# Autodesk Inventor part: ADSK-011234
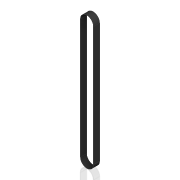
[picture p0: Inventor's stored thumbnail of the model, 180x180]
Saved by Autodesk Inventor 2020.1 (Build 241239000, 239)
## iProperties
Created: 1999-12
Part Number: ADSK-011234
Document SubType Name: Modeling
Designer: sspink
Material: Générique
Density: 1 g/cm^3
Appearance: Rubber-Black
Mass: 105.218 g
Surface Area: 1380.72 cm^2
Volume: 105.218 cm^3
Control State: 0
Master: False
Checked Out: False
Shininess: 0.0
Length Units: 11272
Angle Units: 11279
Time Units: 11290
Mass Units: 11286
Length Display Precision: 3
Angle Display Precision: 2
Compacted: True
Dimensions: 3,2x32,4x1,5 in
Mass: 0,232 lb
DocNumber: ADSK-011234.ipt
Folder: 01 - Themengebiete\Simplification\01 - Packaging machine\
VDS_Category: 3D Komponenten
Density: 0.0
Volumn: 0.0
Area: 0.0
PropertySet Name: Model Information
Author: sspink
Revision Number: -
Title: clutch
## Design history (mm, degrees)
node "Extrusion1" dims "d5" = 38.1635, "d6" = 0
workplane "Arbeitsebene1"
node "Solide1"
node "Corps solides"
node "Corps surfaciques"
sketch "Sketch1"
  geometry: L1 (-16.928, 0)-(-16.928, -741.362); L2 (-15.341, 0)-(-15.341, -741.362); L3 (63.92, 0)-(63.92, -741.362); L4 (65.507, 0)-(65.507, -741.362); A1 r 39.63 centre (24.29, 0) between (63.92, 0) and (-15.341, 0); A2 r 41.218 centre (24.29, 0) between (65.507, 0) and (-16.928, 0); A3 r 39.63 centre (24.29, -741.362) between (-15.341, -741.362) and (63.92, -741.362); A4 r 41.218 centre (24.29, -741.362) between (-16.928, -741.362) and (65.507, -741.362)
  constraints: 8 end point, 8 point on circle, 8 tangent, 4 centre point, 2 coincident, 1 vertical alignment, 1 other
  dimensions: "d0" = 79.2607 diameter of A1; "d1" = 82.4357 diameter of A2; "d2" = 79.2607 diameter of A3 (= d0); "d3" = 82.4357 diameter of A4 (= d1); "d4" = 741.3625 distance of A3.centre A1.centre
